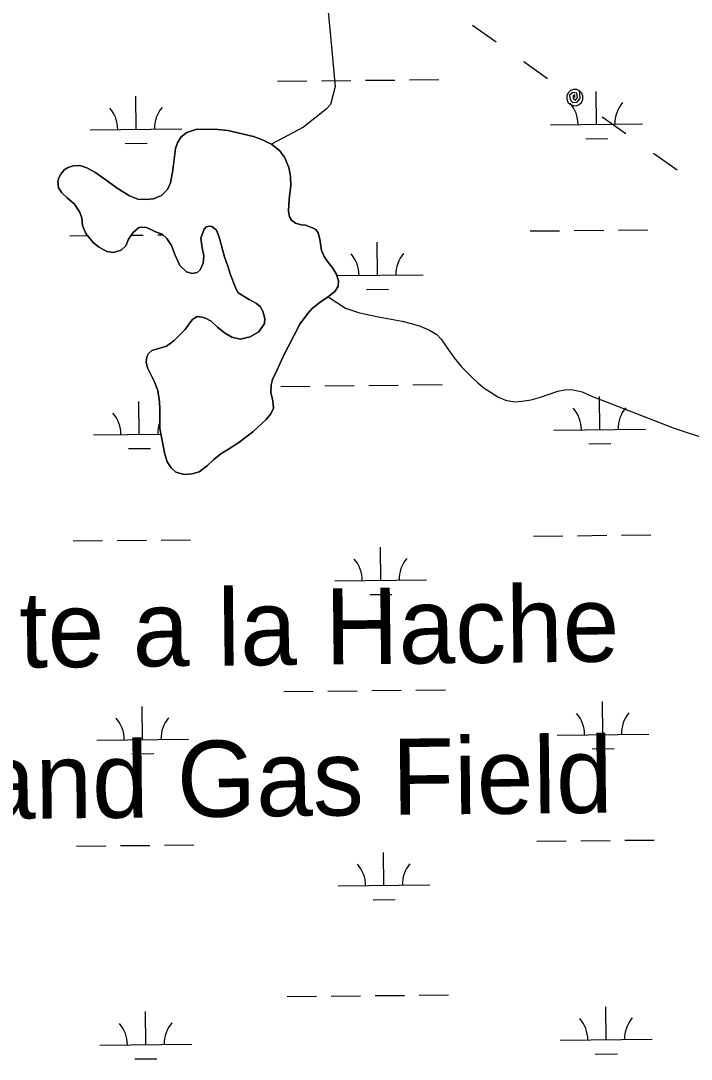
# Model space of a CAD drawing. Extents: x 3734862 to 3772949, y 391520 to 417239.
# Drawn here: x 3765769 to 3766499, y 401776 to 402908 of the extents above; entities that cross this region are included whole.
import ezdxf

# ---------------------------------------------------------------- set-up
doc = ezdxf.new("R2010")
doc.units = 0
for name, color, linetype in [('V-BLDG-IDEN', 7, 'Continuous'), ('V-RIVR-EDGE', 7, 'Continuous'), ('V-TOPO-SHOR', 7, 'Continuous'), ('V-UTIL-LINE', 7, 'Continuous'), ('V-WETL-SWMP', 7, 'Continuous')]:
    doc.layers.add(name, color=color, linetype=linetype)

msp = doc.modelspace()

# ---------------------------------------------------------------- linework, layer by layer
at = {"layer": 'V-RIVR-EDGE'}
msp.add_spline([(3755702.1, 404495.3), (3755757.2, 404470.8), (3755793.3, 404451.2), (3755852.5, 404424.4), (3755881.4, 404415.7), (3755906.2, 404404.4), (3755920.2, 404395.8), (3755948.7, 404379.4), (3755958.2, 404378.9), (3755969, 404378), (3755990.7, 404368.5), (3756022.8, 404350.3), (3756054.8, 404336.6), (3756079.7, 404323), (3756103.6, 404309.4), (3756144.2, 404288), (3756167.7, 404269), (3756188.9, 404253.6), (3756231.4, 404233.1), (3756271.6, 404217.2), (3756299.1, 404203.1), (3756403, 404163.5), (3756460.4, 404140.3), (3756508.7, 404114.9), (3756530.8, 404104), (3756588.2, 404078), (3756639.2, 404052.1), (3756694.3, 404019.5), (3756726.8, 403998.1), (3756735.8, 403989.1), (3756740.3, 403979.6), (3756740.3, 403973.2), (3756740.7, 403967.8), (3756747.5, 403960.5), (3756759.7, 403953.7), (3756786.3, 403941.5), (3756814.3, 403929.2), (3756864.5, 403904.6), (3756889.3, 403896), (3756899.7, 403897.3), (3756908.3, 403901.8), (3756919.2, 403901.3), (3756933.2, 403894.1), (3756945.8, 403892.7), (3756956.2, 403893.1), (3756962.1, 403897.2), (3756970.7, 403896.7), (3756978.4, 403894.4), (3756992.4, 403894.8), (3757002.8, 403897.5), (3757019.1, 403901.5), (3757027.7, 403901.5), (3757034, 403901.1), (3757036.3, 403896.5), (3757036.7, 403891.1), (3757038.5, 403883.4), (3757046.6, 403874.3), (3757060.6, 403866.2), (3757076.4, 403853.9), (3757104.4, 403831.2), (3757122.4, 403816.7), (3757145.5, 403804.5), (3757165.3, 403796.7), (3757181.6, 403787.2), (3757194.2, 403777.7), (3757213.6, 403765.4), (3757229.9, 403756.3), (3757251.6, 403745.9), (3757266.5, 403741.3), (3757283.2, 403734.5), (3757308.9, 403720.9), (3757360.4, 403694.1), (3757393.8, 403670.9), (3757430, 403657.3), (3757461.6, 403645.4), (3757505.4, 403628.1), (3757548.3, 403610.4), (3757591.7, 403587.2), (3757649.5, 403552.3), (3757711.8, 403512.8), (3757753.8, 403493.2), (3757766.9, 403487.8), (3757773.2, 403487.8), (3757785.9, 403494.1), (3757794.5, 403494), (3757803.5, 403489.5), (3757807.1, 403480.9), (3757810.6, 403456), (3757814.2, 403447.9), (3757826.4, 403437), (3757854.4, 403422.9), (3757930.3, 403373.9), (3757975.8, 403342.6), (3758005.2, 403323.5), (3758062.1, 403286.7), (3758092.3, 403263.6), (3758175.8, 403209.6), (3758234.5, 403169.2), (3758283.7, 403133.8), (3758328.8, 403103.4), (3758399.2, 403041.7), (3758421.8, 403023.1), (3758438.1, 403017.7), (3758463.8, 403017.6), (3758491.4, 403026.1), (3758504.5, 403022), (3758513.6, 403014.3), (3758514, 403006.2), (3758499.9, 402997.2), (3758498.1, 402989.9), (3758502.2, 402978.2), (3758510.7, 402969.6), (3758522, 402962.8), (3758545, 402948.7), (3758582.1, 402926.9), (3758650.2, 402878.8), (3758697.6, 402840.7), (3758721.5, 402820.3), (3758740.9, 402809.4), (3758782, 402784.9), (3758831.2, 402755.4), (3758902.1, 402711.8), (3758960.4, 402675.5), (3759018.6, 402634.6), (3759069.6, 402599.7), (3759134.6, 402553.4), (3759185.6, 402508.1), (3759223.5, 402478.1), (3759262.3, 402448.2), (3759321.4, 402402.4), (3759371.5, 402366.1), (3759431.5, 402323.4), (3759463.6, 402300.3), (3759488.9, 402281.7), (3759576.9, 402222.7), (3759627, 402186.8), (3759672.1, 402153.7), (3759778.2, 402087.4), (3759832.8, 402050.7), (3759873, 402019.4), (3759909.5, 401989.4), (3760050.8, 401883.7), (3760100, 401850.2), (3760145.6, 401819.3), (3760185.8, 401788), (3760211.9, 401766.7), (3760254.8, 401734.5), (3760285.5, 401709.1), (3760303.1, 401700.5), (3760325.3, 401691.4), (3760352.8, 401671.4), (3760391.1, 401641), (3760430.4, 401612), (3760461.6, 401590.2), (3760536.9, 401543), (3760583, 401510.8), (3760602.8, 401495.8), (3760629, 401477.2), (3760672.4, 401449.5), (3760711.2, 401426.8), (3760818.6, 401347.8), (3760872.3, 401310.6), (3760925.6, 401271.6), (3760948.6, 401251.7), (3761039.8, 401181.8), (3761107, 401135.5), (3761151.7, 401104.7), (3761172.9, 401093.3), (3761186, 401090.6), (3761199.2, 401092.8), (3761219.5, 401099.1), (3761228.1, 401099.5), (3761233.5, 401095.4), (3761236.7, 401087.7), (3761236.6, 401077.8), (3761228.5, 401063.8), (3761223, 401057.5), (3761223, 401049.3), (3761228.9, 401039.4), (3761242.4, 401026.7), (3761254.1, 401021.7), (3761266.8, 401018.5), (3761292.5, 401001.7), (3761317.3, 400980.4), (3761342.1, 400955.4), (3761463.1, 400853.4), (3761510, 400812.1), (3761550.2, 400777.7), (3761585.3, 400746.8), (3761681.5, 400674.3), (3761756.4, 400618.9), (3761817.8, 400572.2), (3761878.3, 400530.4), (3761996.5, 400436.5), (3762057.4, 400389.8), (3762104.8, 400352.6), (3762156.3, 400313.2), (3762204.5, 400277.3), (3762245.2, 400247.8), (3762291.6, 400210.2), (3762325.9, 400182.1), (3762356.2, 400159.8), (3762404, 400123.6), (3762432.9, 400101.3), (3762455.5, 400091.3), (3762473.5, 400075.9), (3762512.3, 400044.2), (3762551.6, 400012.4), (3762593.6, 399983.8), (3762620.2, 399963.4), (3762661.7, 399937.1), (3762686.6, 399919.8), (3762793.1, 399841.3), (3762834.6, 399812.8), (3762873.4, 399790.1), (3762923.1, 399758.3), (3762957, 399737.4), (3762984, 399721.5), (3763024.2, 399693.4), (3763075.2, 399657.5), (3763115.9, 399633.9), (3763172.8, 399601.2), (3763228.7, 399568.5), (3763285.2, 399533.6), (3763344.3, 399494.1), (3763398.5, 399455.1), (3763444.1, 399421), (3763484.7, 399391.1), (3763603.4, 399303.1), (3763654.8, 399261.8), (3763661.1, 399259.5), (3763667, 399254.5), (3763672, 399245), (3763696.3, 399224.2), (3763722.9, 399200.1), (3763745.5, 399180.2), (3763818.1, 399117.2), (3763841.6, 399099.5), (3763852.4, 399092.2), (3763858.8, 399084.1), (3763875, 399067.3), (3763898, 399046), (3763924.6, 399023.8), (3763949, 399007.9), (3763970.2, 398987.5), (3764004, 398952.6), (3764028.4, 398926.7), (3764056.8, 398899.5), (3764092.9, 398862.4), (3764130.8, 398826.1), (3764147, 398811.6), (3764152.9, 398799.8), (3764162.3, 398783.5), (3764173.6, 398768.6), (3764186.7, 398757.2), (3764206.1, 398746.3), (3764226.9, 398742.2), (3764246.3, 398733.6), (3764269.3, 398717.7), (3764284.2, 398703.2), (3764301.8, 398691.8), (3764323, 398678.2), (3764345.1, 398661), (3764412.4, 398596.6), (3764457, 398559.9), (3764502.6, 398522.7), (3764538.3, 398497.7), (3764566.3, 398486.4), (3764583.9, 398484.5), (3764604.2, 398486.3), (3764616.5, 398486.2), (3764626.4, 398481.7), (3764630.9, 398474.4), (3764636.3, 398461.3), (3764634.9, 398450), (3764631.7, 398441.4), (3764633.1, 398434.7), (3764636.2, 398430.1), (3764643.9, 398425.6), (3764661.1, 398421.5), (3764685.4, 398409.2), (3764715.2, 398382), (3764745.4, 398356.1), (3764793.3, 398328), (3764844.3, 398292.6), (3764885.8, 398258.1), (3764918.8, 398234.5), (3764992.8, 398187.8), (3765058.3, 398144.2), (3765088.1, 398128.3), (3765140.9, 398100.2), (3765168.9, 398079.7), (3765193.7, 398061.6), (3765246.1, 398042), (3765282.2, 398018.4), (3765309.7, 397989.4), (3765340, 397955.4), (3765361.1, 397933.7), (3765382.3, 397911.9), (3765434.7, 397867.9), (3765477.6, 397838.4), (3765508.7, 397823.9), (3765545.3, 397801.2), (3765575.5, 397778), (3765617.5, 397749.9), (3765653.6, 397726.3), (3765681.6, 397710), (3765727.2, 397684.5), (3765762, 397660), (3765771.9, 397659.5), (3765788.2, 397660), (3765793.6, 397658.1), (3765793.6, 397653.6), (3765785.5, 397648.7), (3765785.5, 397645.5), (3765790.9, 397632.8), (3765800.3, 397623.8), (3765814.8, 397612.9), (3765831.9, 397605.6), (3765847.3, 397603.3), (3765858.1, 397598.7), (3765865.8, 397593.3), (3765888.8, 397577), (3765908.7, 397561.5), (3765918.2, 397548.4), (3765919.5, 397542.1), (3765921.3, 397536.2), (3765926.7, 397533.5), (3765933, 397534.4), (3765940.7, 397533.4), (3765944.8, 397530.3), (3765957, 397519.4), (3765987.7, 397499.9), (3766024.7, 397468.1), (3766059.4, 397438.2), (3766085.1, 397413.3), (3766102.7, 397400.1), (3766131.6, 397377.4), (3766172.7, 397350.2), (3766210.6, 397318.9), (3766264.3, 397285.3), (3766306.8, 397260.8), (3766362.7, 397220.8), (3766381.1, 397208.5)], degree=3, dxfattribs=at)
at = {"layer": 'V-TOPO-SHOR'}
for points in [[(3765779.2, 403851.9), (3765888.1, 403813.9), (3765942.7, 403774.2), (3765982.3, 403744.5), (3766012.1, 403704.8), (3766027, 403655.2), (3766031.9, 403565.9), (3766046.8, 403501.5), (3766071.6, 403442), (3766071.6, 403382.4), (3766081.5, 403332.8), (3766111.3, 403278.3), (3766121.2, 403248.5), (3766121.2, 403208.9), (3766116.2, 403139.4), (3766116.2, 403084.9), (3766096.4, 402985.7), (3766101.4, 402941.1), (3766106.3, 402891.5), (3766111.3, 402836.9), (3766106.3, 402817.1), (3766101.4, 402812.1), (3766076.6, 402792.3), (3766041.8, 402773.7)], [(3765835, 402693.5), (3765832.7, 402700), (3765827.3, 402708.4), (3765819.1, 402715.5), (3765813.3, 402720.8), (3765809.6, 402726.3), (3765809.1, 402733), (3765810.1, 402737.3), (3765812.3, 402741), (3765815.8, 402745.8), (3765820.1, 402748.3), (3765825.6, 402750.1), (3765832.8, 402750.6), (3765840.4, 402748), (3765849.2, 402743.5), (3765860.3, 402735.8), (3765873.5, 402725.7), (3765887.1, 402717.6), (3765896.3, 402714), (3765904.5, 402713.4), (3765913.1, 402714.3), (3765922.1, 402718), (3765928.6, 402724.6), (3765931.6, 402731.6), (3765934, 402743.5), (3765935.6, 402756.8), (3765937.3, 402769.1), (3765939.3, 402775.3), (3765943.4, 402781.7), (3765949.7, 402786.6), (3765959.3, 402789.8), (3765972.2, 402790.1), (3765983.5, 402789.9), (3765994.3, 402788.6), (3766022.4, 402782.2), (3766030.2, 402779.2), (3766041.8, 402773.7), (3766050.6, 402766.8), (3766056.2, 402759.5), (3766060.6, 402748.3), (3766062.5, 402739.1), (3766063, 402728.4), (3766061.4, 402717.3), (3766060.8, 402708.9), (3766060.5, 402700.3), (3766061.4, 402694.8), (3766063.8, 402691.1), (3766068, 402687.7), (3766074.3, 402685.9), (3766079, 402685.5), (3766086.4, 402682.7), (3766090.1, 402680.7), (3766092.8, 402677.2), (3766094.7, 402670.3), (3766096.4, 402658), (3766099.3, 402651.2), (3766103.1, 402645.9), (3766108.9, 402638.8), (3766112.6, 402631.9), (3766115.1, 402624.9), (3766114.5, 402619.2), (3766111.3, 402613.4), (3766103.5, 402607.4), (3766095.4, 402602), (3766085.8, 402594.4), (3766081.3, 402588.8), (3766072.8, 402577.5)], [(3766072.8, 402577.5), (3766054.4, 402541.5), (3766048.2, 402527.8), (3766043.1, 402517.1), (3766041.7, 402511.5), (3766041, 402503.1), (3766043.3, 402494.1), (3766043.9, 402486.1), (3766041.3, 402480), (3766036, 402473.6), (3766021.6, 402460.2), (3766006.3, 402448.6), (3765995.1, 402441.2), (3765986.7, 402436.2), (3765979.2, 402430), (3765972.1, 402423.4), (3765963.1, 402416.5), (3765955.3, 402414.4), (3765946.5, 402413.8), (3765937.7, 402416.4), (3765932.6, 402420.8), (3765928, 402427.4), (3765925.1, 402437.2), (3765922.7, 402450.7), (3765920, 402464), (3765920.1, 402475.9), (3765920.2, 402484.7), (3765919.8, 402492.9), (3765917.8, 402505.4), (3765914.1, 402515.4), (3765911.2, 402521.1), (3765906.6, 402529.9), (3765905.3, 402536.2), (3765905.9, 402541.9), (3765907.7, 402545.6), (3765911.6, 402548.9), (3765920, 402551.5), (3765927.3, 402553.6), (3765935.3, 402559.3), (3765940.4, 402564.5), (3765947.7, 402571.9), (3765953, 402579.1), (3765955.8, 402582.6), (3765960.7, 402585.7), (3765960.7, 402585.9), (3765965.8, 402585.2), (3765969.9, 402584.2), (3765976.1, 402580.7), (3765982.9, 402574.4), (3765990.7, 402568.3), (3765998.8, 402563.5), (3766007.6, 402561.3), (3766018.6, 402563.8), (3766028.2, 402569.2), (3766034.1, 402578.3), (3766034.7, 402583.6), (3766032.6, 402591.8), (3766029.5, 402596.7), (3766025.7, 402600.3), (3766017.5, 402604.6), (3766005.4, 402611.7), (3766003.3, 402615.9), (3766000.6, 402623.1), (3765996.9, 402632.5), (3765994.5, 402639.7), (3765990.8, 402650.9), (3765984.7, 402672.6), (3765981.8, 402680.1), (3765977, 402684.2), (3765974, 402684.4), (3765970.7, 402683.7), (3765968.4, 402681.3), (3765965, 402671.4), (3765966.3, 402660.8), (3765968, 402652), (3765967.3, 402644.2), (3765964, 402636.8), (3765961, 402634.1), (3765955.3, 402632.8), (3765949.3, 402634.8), (3765942.1, 402641.7), (3765936.5, 402653.6), (3765932.9, 402663.4), (3765927.8, 402670.9), (3765922.6, 402675.6), (3765915.6, 402678.4), (3765910.9, 402680.5), (3765905.5, 402682.9), (3765899.4, 402683.4), (3765896.9, 402682.6), (3765891.2, 402677.7), (3765886, 402670.2), (3765883.1, 402663.1), (3765877.9, 402658.1), (3765869.5, 402655.6), (3765862.5, 402656.8), (3765853.4, 402662), (3765847.3, 402666.5), (3765839.6, 402676.3), (3765835.9, 402685.3), (3765835, 402693.5)], [(3766103.5, 402607.4), (3766122.5, 402594.9), (3766136.6, 402590.2), (3766147.9, 402587.6), (3766160.4, 402585.1), (3766184.2, 402580.7), (3766194.3, 402578.5), (3766203.9, 402575.3), (3766214.2, 402571.1), (3766222, 402566.2), (3766226.8, 402561.2), (3766234.8, 402549.5), (3766241, 402541), (3766248.9, 402531), (3766259.4, 402520.4), (3766266.8, 402513.7), (3766273.7, 402507.8), (3766281.5, 402503.1), (3766288.5, 402498.3), (3766296.9, 402494.6), (3766306.7, 402493.1), (3766314.9, 402493.5), (3766324.9, 402495.1), (3766335.2, 402498), (3766354, 402504.7), (3766363.4, 402506.4), (3766370.6, 402506), (3766380.6, 402503.8), (3766392.7, 402498.4), (3766406.1, 402493.2), (3766479.6, 402464.6), (3766597.5, 402425.8)]]:
    msp.add_lwpolyline(points, dxfattribs=at)
at = {"layer": 'V-UTIL-LINE'}
for points in [[(3766260.9, 402903.6), (3766286.7, 402885.3)], [(3766317.1, 402863.9), (3766342.9, 402845.6)], [(3766372.6, 402824.6), (3766372.6, 402827.5), (3766370.7, 402826.2), (3766370.7, 402823.5), (3766373.3, 402822), (3766375.4, 402824.7), (3766374.7, 402829.4), (3766370.5, 402830.1), (3766366.7, 402827.1), (3766367.3, 402822.5), (3766370.3, 402819.2), (3766375.1, 402819.6), (3766378.5, 402823.9), (3766377.8, 402832), (3766374.6, 402833.4), (3766371.1, 402833.5), (3766367.8, 402832.2), (3766365.2, 402829.8), (3766363.8, 402826.6), (3766363.7, 402823.1), (3766365, 402819.8), (3766367.4, 402817.3), (3766370.6, 402815.9), (3766374.1, 402815.8), (3766377.4, 402817), (3766379.9, 402819.4), (3766381.4, 402822.6), (3766381.4, 402826.2), (3766380.2, 402829.4), (3766377.8, 402832)], [(3766402.2, 402803.7), (3766428, 402785.4)], [(3766458.4, 402763.9), (3766484.2, 402745.7)]]:
    msp.add_lwpolyline(points, dxfattribs=at)
at = {"layer": 'V-WETL-SWMP'}
for p, q in [((3766048.4, 402842.5), (3766080.4, 402842.8)), ((3766096.4, 402843), (3766128.4, 402843.3)), ((3766144.4, 402843.5), (3766176.4, 402843.8)), ((3766192.4, 402844), (3766224.3, 402844.3)), ((3766396.2, 402795.4), (3766395.8, 402831.4)), ((3765894.3, 402790.1), (3765893.9, 402826.1)), ((3765844.3, 402789.6), (3765944.3, 402790.6)), ((3766346.2, 402794.9), (3766446.2, 402795.9)), ((3765882.5, 402774.5), (3765906.5, 402774.8)), ((3766384.4, 402779.8), (3766408.4, 402780.1)), ((3765822.1, 402673.9), (3765841.3, 402674.1)), ((3765889, 402674.6), (3765902.1, 402674.7)), ((3765918.1, 402674.9), (3765923.3, 402674.9)), ((3766324, 402679.2), (3766356, 402679.5)), ((3766372, 402679.7), (3766404, 402680)), ((3766420, 402680.2), (3766452, 402680.5)), ((3766157.4, 402631), (3766157.1, 402667)), ((3766113.1, 402630.5), (3766207.4, 402631.5)), ((3766145.6, 402615.4), (3766169.6, 402615.7)), ((3766051.9, 402509.8), (3766083.9, 402510.1)), ((3766099.9, 402510.3), (3766131.9, 402510.6)), ((3766147.9, 402510.8), (3766179.9, 402511.1)), ((3766195.9, 402511.3), (3766227.9, 402511.7)), ((3765897.8, 402457.4), (3765897.4, 402493.4)), ((3766399.7, 402462.7), (3766399.3, 402498.7)), ((3765847.8, 402456.9), (3765921.3, 402457.7)), ((3766349.7, 402462.2), (3766449.7, 402463.3)), ((3766387.9, 402447.2), (3766411.9, 402447.4)), ((3765886, 402441.9), (3765910, 402442.1)), ((3766327.5, 402346.5), (3766359.5, 402346.9)), ((3766375.5, 402347), (3766407.5, 402347.4)), ((3766423.5, 402347.5), (3766455.5, 402347.9)), ((3765825.6, 402341.2), (3765857.6, 402341.6)), ((3765873.6, 402341.7), (3765905.6, 402342.1)), ((3765921.6, 402342.2), (3765953.6, 402342.6)), ((3766161, 402298.3), (3766160.6, 402334.3)), ((3766111, 402297.8), (3766211, 402298.9)), ((3766149.1, 402282.8), (3766173.1, 402283)), ((3766055.4, 402177.1), (3766087.4, 402177.5)), ((3766103.4, 402177.6), (3766135.4, 402178)), ((3766151.4, 402178.2), (3766183.4, 402178.5)), ((3766199.4, 402178.7), (3766231.4, 402179)), ((3766403.2, 402130.1), (3766402.8, 402166.1)), ((3765901.3, 402124.8), (3765901, 402160.8)), ((3766353.2, 402129.5), (3766453.2, 402130.6)), ((3765851.3, 402124.2), (3765951.3, 402125.3)), ((3765889.5, 402109.2), (3765913.5, 402109.5)), ((3766391.4, 402114.5), (3766415.4, 402114.8)), ((3765829.2, 402008.6), (3765861.2, 402008.9)), ((3765877.2, 402009.1), (3765909.2, 402009.4)), ((3765925.1, 402009.6), (3765957.1, 402009.9)), ((3766331, 402013.9), (3766363, 402014.2)), ((3766379, 402014.4), (3766411, 402014.7)), ((3766427, 402014.9), (3766459, 402015.2)), ((3766164.5, 401965.7), (3766164.1, 402001.7)), ((3766114.5, 401965.1), (3766214.5, 401966.2)), ((3766152.6, 401950.1), (3766176.6, 401950.4)), ((3766202.9, 401846), (3766234.9, 401846.3)), ((3766058.9, 401844.5), (3766090.9, 401844.8)), ((3766106.9, 401845), (3766138.9, 401845.3)), ((3766154.9, 401845.5), (3766186.9, 401845.8)), ((3765904.9, 401792.1), (3765904.5, 401828.1)), ((3766406.7, 401797.4), (3766406.4, 401833.4)), ((3765854.9, 401791.6), (3765954.9, 401792.6)), ((3766356.7, 401796.9), (3766456.7, 401797.9)), ((3766394.9, 401781.9), (3766418.9, 401782.1)), ((3765893, 401776.6), (3765917, 401776.8))]:
    msp.add_line(p, q, dxfattribs=at)
for points in [[(3766114.5, 402619.2), (3766115.1, 402624.9), (3766112.6, 402631.9), (3766108.9, 402638.8), (3766103.1, 402645.9), (3766099.2, 402651.2), (3766096.4, 402658), (3766094.7, 402670.3), (3766092.8, 402677.2), (3766090.1, 402680.7), (3766086.4, 402682.7), (3766079, 402685.5), (3766074.3, 402685.9), (3766068, 402687.7), (3766063.8, 402691.1), (3766061.4, 402694.8), (3766060.5, 402700.3), (3766060.8, 402708.9), (3766061.4, 402717.3), (3766063, 402728.4), (3766062.5, 402739.1), (3766060.6, 402748.3), (3766056.2, 402759.5), (3766050.6, 402766.8), (3766041.8, 402773.7), (3766030.2, 402779.2), (3766022.4, 402782.2), (3765994.3, 402788.6), (3765983.5, 402789.9), (3765972.2, 402790.1), (3765959.3, 402789.8), (3765949.7, 402786.6), (3765943.4, 402781.7), (3765939.3, 402775.3), (3765937.3, 402769.1), (3765934, 402743.5), (3765931.6, 402731.6), (3765928.6, 402724.6), (3765922.1, 402718), (3765913.1, 402714.3), (3765904.5, 402713.4), (3765896.3, 402714), (3765887.1, 402717.6), (3765873.5, 402725.7), (3765860.3, 402735.8), (3765849.2, 402743.5), (3765840.4, 402748), (3765832.8, 402750.6), (3765825.6, 402750.1), (3765820.1, 402748.3), (3765815.8, 402745.8), (3765812.3, 402741), (3765810.1, 402737.3), (3765809.1, 402733), (3765809.6, 402726.3), (3765813.3, 402720.8), (3765819.1, 402715.5), (3765827.3, 402708.4), (3765832.7, 402700), (3765835, 402693.5), (3765835.9, 402685.3), (3765839.6, 402676.3)], [(3765839.6, 402676.3), (3765847.3, 402666.5), (3765853.4, 402662), (3765862.5, 402656.8), (3765869.5, 402655.6), (3765877.9, 402658.1), (3765883.1, 402663.1), (3765886, 402670.2), (3765891.2, 402677.7), (3765896.9, 402682.6), (3765899.4, 402683.4), (3765905.5, 402682.9), (3765910.9, 402680.5), (3765915.6, 402678.4), (3765922.6, 402675.6), (3765927.8, 402670.9), (3765932.9, 402663.4), (3765936.5, 402653.6), (3765942.1, 402641.7), (3765949.3, 402634.8), (3765955.3, 402632.8), (3765961, 402634.1), (3765964, 402636.8), (3765967.3, 402644.2), (3765968, 402652), (3765966.3, 402660.8), (3765965, 402671.4), (3765968.4, 402681.3), (3765970.7, 402683.7), (3765974, 402684.4), (3765977, 402684.2), (3765981.8, 402680.1), (3765984.7, 402672.6), (3765990.8, 402650.9), (3765994.5, 402639.7), (3765996.9, 402632.5), (3766000.6, 402623.1), (3766003.3, 402615.9), (3766005.4, 402611.7), (3766017.5, 402604.6), (3766025.7, 402600.3), (3766029.5, 402596.7), (3766032.6, 402591.8), (3766034.7, 402583.6), (3766034.1, 402578.3), (3766028.2, 402569.2), (3766018.6, 402563.8), (3766007.6, 402561.3), (3765998.8, 402563.5), (3765990.7, 402568.3), (3765982.9, 402574.4), (3765976.1, 402580.7), (3765969.9, 402584.2), (3765965.8, 402585.2), (3765960.7, 402585.9), (3765955.8, 402582.6), (3765953, 402579.1), (3765947.7, 402571.9), (3765935.3, 402559.3), (3765927.3, 402553.6), (3765920, 402551.5), (3765911.6, 402548.9), (3765907.7, 402545.6), (3765905.9, 402541.9), (3765905.3, 402536.2), (3765906.6, 402529.9), (3765914.1, 402515.4), (3765917.8, 402505.4), (3765919.8, 402492.9), (3765920.2, 402484.7), (3765920, 402464), (3765922.7, 402450.7), (3765925.1, 402437.2), (3765928, 402427.4), (3765932.6, 402420.8), (3765937.7, 402416.4), (3765946.5, 402413.8), (3765955.3, 402414.4), (3765963.1, 402416.5), (3765972.1, 402423.4), (3765979.2, 402430), (3765986.7, 402436.2), (3765995.1, 402441.2), (3766006.3, 402448.6), (3766021.6, 402460.2), (3766036, 402473.6), (3766041.3, 402480), (3766043.9, 402486.1), (3766043.3, 402494.1), (3766041, 402503.1), (3766041.7, 402511.5), (3766043.1, 402517.1), (3766048.2, 402527.8), (3766054.4, 402541.5), (3766072.8, 402577.5), (3766081.3, 402588.8), (3766085.8, 402594.4), (3766095.4, 402602), (3766103.5, 402607.4), (3766111.3, 402613.4), (3766114.5, 402619.2)]]:
    msp.add_lwpolyline(points, dxfattribs=at)
for centre, start, end in [((3765839.1, 402790), 359.8334, 41.377), ((3765949.5, 402791.1), 139.8334, 181.377), ((3766340.9, 402795.3), 359.8334, 41.377), ((3766451.4, 402796.4), 139.8334, 181.377), ((3766102.2, 402630.9), 359.8334, 41.377), ((3766212.7, 402632), 139.8334, 181.377), ((3765842.6, 402457.3), 359.8334, 41.377), ((3766344.5, 402462.6), 359.8334, 41.377), ((3766454.9, 402463.8), 139.8334, 181.377), ((3765953.1, 402458.5), 159.3272, 181.377), ((3766216.2, 402299.4), 139.8334, 181.377), ((3766105.7, 402298.2), 359.8334, 41.377), ((3766348, 402130), 359.8334, 41.377), ((3766458.5, 402131.1), 139.8334, 181.377), ((3765846.1, 402124.7), 359.8334, 41.377), ((3765956.6, 402125.8), 139.8334, 181.377), ((3766109.2, 401965.6), 359.8334, 41.377), ((3766219.7, 401966.7), 139.8334, 181.377), ((3765849.6, 401792), 359.8334, 41.377), ((3765960.1, 401793.2), 139.8334, 181.377), ((3766351.5, 401797.3), 359.8334, 41.377), ((3766462, 401798.5), 139.8334, 181.377)]:
    msp.add_arc(centre, 35.2, start, end, dxfattribs=at)

# ---------------------------------------------------------------- texts
at = {"layer": 'V-BLDG-IDEN'}
for s, p in [('Pointe a la Hache', (3765545.3, 402200.7)), ('Oil and Gas Field', (3765556.7, 402036.1))]:
    msp.add_text(s, height=83, rotation=0.6, dxfattribs=at).set_placement(p)

doc.saveas('drawing.dxf')
